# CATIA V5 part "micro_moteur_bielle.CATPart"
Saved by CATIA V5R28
Part number: Part5
Bounding box of the stored display mesh (mm): x -3 to 3, y -5 to 5, z -4.99 to 38.541
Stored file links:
  D:\SAVE\Mécanique\Cotation ISO\Cotation GPS Exercices\Exo 1 ISO GPS\exo2_bielle.CATPart
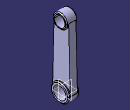
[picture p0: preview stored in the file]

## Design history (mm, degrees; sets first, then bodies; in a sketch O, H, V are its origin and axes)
Body1 (main body)
  Sketch1 on yz-plane, origin (0, 0, 0), H (0, 1, 0), V (0, 0, 1)
    arc A1 centre (0, 0) radius 5 from (-4.9979, 0.1447) to (4.9979, 0.1447) ccw
    arc A2 centre (0, 34.5507) radius 4 from (3.9983, 34.6665) to (-3.9983, 34.6665) ccw
    point P1 (0, 34.5507)
    line L1 (3.9983, 34.6665) -> (4.9979, 0.1447)
    point P2 (3.9983, 34.6665)
    line L2 (-3.9983, 34.6665) -> (-4.9979, 0.1447)
    point P4 (-3.9983, 34.6665)
    point P6 (-3.9983, 34.6665)
    point P7 (3.9983, 34.6665)
    radius A1 = 5
    radius A2 = 4
    coincidence: P1 V, A2 P2, A2 P4, L2 P6, L1 P7, P2 P7, P4 P6
    tangency: L1 A2, L1 A1, L2 A2, L2 A1
  Pad1: profile Sketch1, direction (1, 0, 0), length 2, mirrored extent
  Sketch2 on yz-plane, origin (0, 0, 0), H (0, 1, 0), V (0, 0, 1)
    circle A1 centre (0, 0) radius 5
    circle A2 centre (0, 34.5507) radius 4
    point P1 (0, 34.5507)
    reference projected arc E1 centre (0, 34.5507) radius 4 from (3.9992, 34.6311) to (-3.9992, 34.6311) ccw from edge [face of Pad1 from Sketch1.A2 | end face of Pad1]
    radius A1 = 5
    coincidence: P1 V
    tangency: A2 E1
  Pad2: profile Sketch2, direction (1, 0, 0), length 3, mirrored extent
  Sketch3 on yz-plane, origin (0, 0, 0), H (0, 1, 0), V (0, 0, 1)
    circle A1 centre (0, 0) radius 3.5
    circle A2 centre (0, 34.5507) radius 3
    point P1 (0, 34.5507)
    reference projected circle E1 centre (0, 34.5507) radius 4 from edge [face of Pad2 from Sketch2.A2 | end face of Pad2]
    radius A1 = 3.5
    radius A2 = 3
    coincidence: P1 V
    concentricity: A2 E1
  Pocket1: profile Sketch3, direction (-1, 0, 0), length 4, mirrored extent
  Chamfer1: length 0.5, angle 45, on edge [face of Pad2 from Sketch2.A2 | end face of Pad2]; edge [start face of Pad2 | face of Pad2 from Sketch2.A2]; edge [face of Pad2 | end face of Pad2]; edge [start face of Pad2 | face of Pad2]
